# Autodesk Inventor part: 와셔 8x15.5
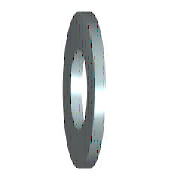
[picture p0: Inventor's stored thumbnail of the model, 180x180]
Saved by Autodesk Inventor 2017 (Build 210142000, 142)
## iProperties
Created: 2012-02
Part Number: 와셔 8x15.5
Material: 강철, 연강
Description: 평면 와셔
Document SubType Name: Modeling
Standard: KS B 1326
Designer: mduedu
Standards Organization: KS
Language: ko-KR
Size Designation: 8x15.5
Categories: <MemberInstance><Categories><Category DisplayName="조임쇠" InternalName="e4da775c-781d-43d5-af7c-5136215cf5a6" Mnemonic="FSTN"><Category DisplayName="와셔" InternalN
Density: 7.86 g/cm^3
Mass: 1.67606 g
Surface Area: 3.86683 cm^2
Volume: 0.213239 cm^3
Appearance: 노란색
IsCustomPart: 1
Author: mduedu
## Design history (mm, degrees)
sketch "스케치"
  geometry: C1 r 7.75 at (0, 0); C2 r 4.2 at (0, 0); 1 further point
  constraints: 2 centre point, 2 coincident
  dimensions: "d0" = 8.4 diameter of C2 (= SD1); "d1" = 15.5 diameter of C1 (= SD2)
extrude "본체" new body sketch "스케치" distance "d2" = 1.6 (= SD); taper "d3" = 0 deg
workaxis "Work Axis1"
workplane "Work Plane1"
body "Solid1"
other parameters: "SD1" = 8.4 [user parameter; used in 1 equation term], "SD2" = 15.5 [user parameter; used in 1 equation term], "SD" = 1.6 [user parameter; used in 1 equation term], "d4" = 0, "d5" = 0, "d6" = 0, "d7" = 0, "NND" = 8 [user parameter]
